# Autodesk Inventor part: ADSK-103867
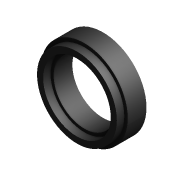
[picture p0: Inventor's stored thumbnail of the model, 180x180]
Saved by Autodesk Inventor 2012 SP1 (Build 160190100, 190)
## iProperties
Shininess: 0.0
Created: 2000-11
Part Number: ADSK-103867
Document SubType Name: Modeling
Stock Number: ADSK-103867
Density: 1 g/cm^3
Material: Default
Density: 0.0
Volumn: 0.0
Area: 0.0
PropertySet Name: Model Information
Control State: 0
Master: False
Checked Out: False
Author: gao
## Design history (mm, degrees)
node "Extrusion1" dims "d2" = 29.0068, "d3" = 0
  sketch "Sketch1"
    geometry: C1 r 47.625 at (-0.585, 0); C2 r 67.374 at (-0.585, 0)
    constraints: 2 centre point, 1 coincident
    dimensions: "d0" = 95.25 diameter of C1; "d1" = 134.747 diameter of C2
node "Extrusion2" dims "d6" = 11.4808, "d7" = 0
  sketch "Sketch2"
    geometry: C1 r 67.374 at (0, 0) reference; C2 r 52.388 at (0, 0); C3 r 61.913 at (0, 0)
    constraints: 2 centre point, 2 coincident
    dimensions: "d4" = 104.775 diameter of C2; "d5" = 123.825 diameter of C3
body "Solid1"
